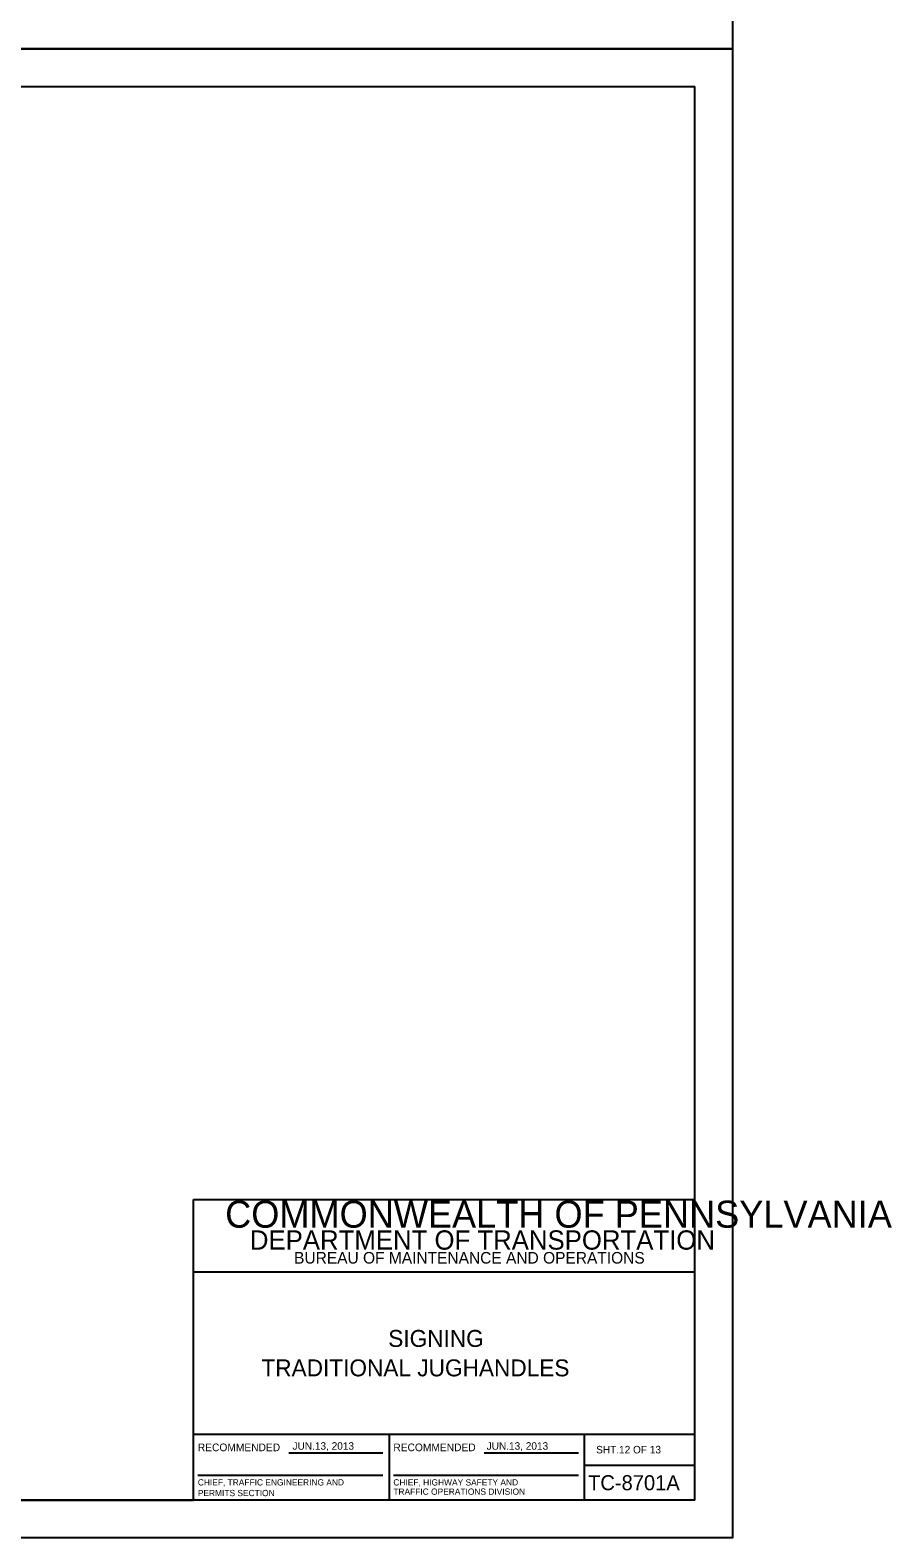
# Model space of a CAD drawing. Extents: x 644898 to 648326, y 298294 to 300670.
# Drawn here: x 647982 to 648326, y 298888 to 299490 of the extents above; entities that cross this region are included whole.
import ezdxf

# ---------------------------------------------------------------- set-up
doc = ezdxf.new("R2010")
doc.units = 0
for name, color, linetype in [('1', 7, 'Continuous'), ('2', 7, 'Continuous'), ('XCS-GRID-MIN', 7, 'Continuous')]:
    doc.layers.add(name, color=color, linetype=linetype)

msp = doc.modelspace()

# ---------------------------------------------------------------- linework, layer by layer
at = {"layer": '1'}
for p, q in [((647461.32, 299467.49), (648247.32, 299467.49)), ((648247.32, 298903.49), (648247.32, 299467.49)), ((648047.32, 298903.49), (648047.32, 299023.49)), ((648047.32, 299023.49), (648247.32, 299023.49)), ((648247.32, 298994.49), (648047.32, 298994.49)), ((648047.32, 298929.87), (648247.32, 298929.87)), ((648125.32, 298929.87), (648125.32, 298903.49)), ((648203.2, 298903.49), (648203.2, 298929.87)), ((648085.26, 298922.44), (648122.88, 298922.44)), ((648163.26, 298922.44), (648200.88, 298922.44)), ((648203.2, 298917.49), (648247.32, 298917.49)), ((648049.01, 298913.54), (648122.88, 298913.54)), ((648127.01, 298913.54), (648200.88, 298913.54)), ((648247.32, 298903.49), (647461.32, 298903.49)), ((647461.32, 298903.49), (648047.32, 298903.49))]:
    msp.add_line(p, q, dxfattribs=at)
at = {"layer": 'XCS-GRID-MIN'}
for points in [[(647421.32, 300076.49), (648262.32, 300076.49), (648262.32, 299482.49), (647421.32, 299482.49)], [(647421.32, 299482.49), (648262.32, 299482.49), (648262.32, 298888.49), (647421.32, 298888.49)]]:
    msp.add_lwpolyline(points, close=True, dxfattribs=at)

# ---------------------------------------------------------------- texts
at = {"layer": '1'}
for s, height, p in [('COMMONWEALTH OF PENNSYLVANIA', 10.7828, (648059.92, 299012.23)), ('DEPARTMENT OF TRANSPORTATION', 7.6837, (648069.78, 299003.48)), ('BUREAU OF MAINTENANCE AND OPERATIONS', 4.6253, (648087.42, 298997.91)), ('SIGNING', 6.75, (648124.97, 298964.68)), ('TRADITIONAL JUGHANDLES', 6.75, (648074.38, 298952.93)), ('RECOMMENDED', 3.048, (648049.01, 298923.07)), ('RECOMMENDED', 3.048, (648127.01, 298923.07)), ('SHT.12 OF 13', 3, (648207.91, 298922.18)), ('CHIEF, TRAFFIC ENGINEERING AND', 2.5, (648049.01, 298909.38)), ('CHIEF, HIGHWAY SAFETY AND', 2.5, (648127.01, 298909.38)), ('TC-8701A', 6, (648204.69, 298907.49)), ('PERMITS SECTION', 2.5, (648049.01, 298905.13)), ('TRAFFIC OPERATIONS DIVISION', 2.5, (648127.01, 298905.68))]:
    msp.add_text(s, height=height, dxfattribs=at).set_placement(p)
at = {"layer": '2'}
for p in [(648086.79, 298923.65), (648164.24, 298923.65)]:
    msp.add_text('JUN.13, 2013', height=3, dxfattribs=at).set_placement(p)

doc.saveas('drawing.dxf')
